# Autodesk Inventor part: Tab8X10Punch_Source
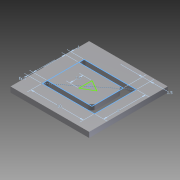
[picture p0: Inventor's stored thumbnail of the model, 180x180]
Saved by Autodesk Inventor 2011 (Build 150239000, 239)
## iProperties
Created: 2007-02
Part Number: Tab8X10Punch_Source
Material: Default
Document SubType Name: Sheet Metal
Designer: Autodesk, Inc.
Mass: 0.195785 g
Surface Area: 5.02854 cm^2
Volume: 0.195785 cm^3
Density: 1 g/cm^3
Sheet Metal Rule: 1 mm
Author: Autodesk, Inc.
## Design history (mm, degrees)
node "Face1"
  sketch "Sketch1"
    geometry: L1 (-7.5, 7.5)-(7.5, 7.5); L2 (7.5, 7.5)-(7.5, -7.5); L3 (7.5, -7.5)-(-7.5, -7.5); L4 (-7.5, -7.5)-(-7.5, 7.5); L5 (-7.5, 7.5)-(7.5, -7.5); 2 further points
    constraints: 10 end point, 2 parallel, 1 coincident, 1 horizontal, 1 midpoint, 1 perpendicular
    dimensions: "d0" = 15 distance of L2.end L3.end; "d1" = 15 distance of L1.end L2.end (= d0)
sketch "Sketch2"
  geometry: L1 (-4.5, 4)-(5, 4); L2 (5, 4)-(5, -4); L3 (5, -4)-(-4.5, -4); L4 (-4.5, -3)-(2.5, -3); L5 (-5, 3.5)-(-5, 3.5); L6 (-5, -3.5)-(-5, -3.5); L7 (-5, -4)-(5, 4); L8 (3.5, 2)-(3.5, -2); L9 (4, 3)-(3.75, 3); L10 (2.5, 3)-(-4.5, 3); A1 r 0.5 centre (-4.5, 3.5) between (-4.5, 4) and (-5, 3.5); A2 r 0.5 centre (-4.5, 3.5) between (-5, 3.5) and (-4.5, 3); A3 r 0.5 centre (-4.5, -3.5) between (-4.5, -3) and (-5, -3.5); A4 r 0.5 centre (-4.5, -3.5) between (-5, -3.5) and (-4.5, -4); A5 r 1 centre (2.5, 2) between (3.5, 2) and (2.5, 3); A6 r 1 centre (2.5, -2) between (2.5, -3) and (3.5, -2); 6 further points
  constraints: 20 end point, 12 point on circle, 12 tangent, 9 point on line, 6 centre point, 4 equal radius, 4 perpendicular, 3 parallel, 2 coincident, 2 collinear, 1 horizontal, 1 midpoint
  dimensions: "d16" = 10 distance of L2.end L7.start; "d17" = 8 distance of L1.end L2.end; "d19" = 1.5 distance between parallel lines of L2 L8; "d20" = 1 distance between parallel lines of L10 L1; "d21" = 1 distance between parallel lines of L3 L4; "d22" = 0.5 radius of A1; "d23" = 1 radius of A5
cut "Cut1" sketch "Sketch2" dims "d3" = 1 (= Thickness), "d4" = 0
body "Solid1"
sketch "Sketch3"
  geometry: L1 (-5, 4)-(5, 4); L2 (5, 4)-(5, -4); L3 (5, -4)-(-5, -4); L4 (-5, -4)-(-5, 4); L5 (-5, -4)-(5, 4); L6 (-5, 3)-(3.5, 3); L7 (3.5, 3)-(3.5, -3); L8 (3.5, -3)-(-5, -3); L9 (1.443, 0)-(-0.722, -1.25); L10 (-0.722, -1.25)-(-0.722, 1.25); L11 (-0.722, 1.25)-(1.443, 0); 4 further points
  constraints: 22 end point, 3 coincident, 3 parallel, 3 perpendicular, 2 point on line, 1 horizontal, 1 midpoint, 7 other
  dimensions: "d24" = 10 distance of L2.end L3.end; "d25" = 8 distance of L1.end L2.end; "d26" = 1 distance between parallel lines of L1 L6; "d27" = 1 distance between parallel lines of L3 L8 (= d26); "d28" = 1.5 distance between parallel lines of L2 L7; "d29" = 2.5 distance of L9.end L10.end
face "Plate1" dims "Thickness" = 1
other parameters: "BendRadius" = 0.5, "BendReliefWidth" = 1 (= Thickness), "BendReliefDepth" = 0.5 (= 0.5 x Thickness), "CornerReliefSize" = 4 (= 4 x Thickness), "SeamGap" = 0.01, "MinimumRemnant" = 2 (= 2 x Thickness), "TransitionRadius" = 0.5 (= BendRadius), "JacobiRadiusSize" = 1 (= Thickness), "d2" = 0.5 (= BendRadius), "d18" = 1, "GapSize" = 1 (= Thickness)
